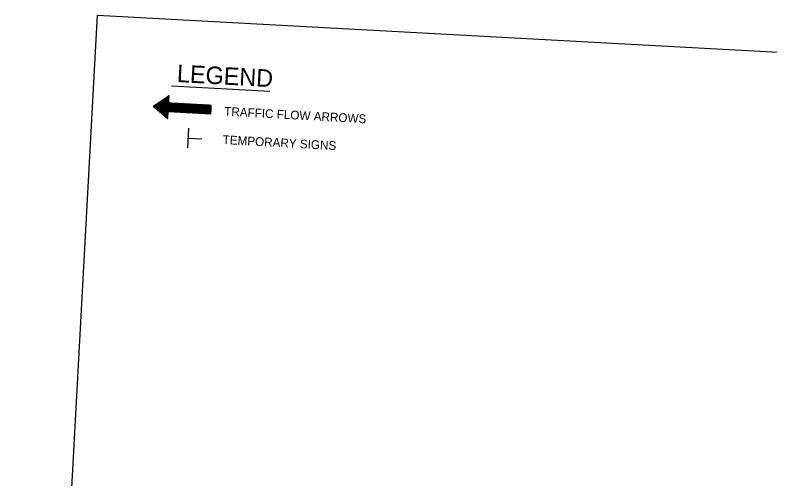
# Model space of a CAD drawing. Extents: x 879461 to 881100, y 1566470 to 1567598.
# Drawn here: x 879461 to 879979, y 1567279 to 1567598 of the extents above; entities that cross this region are included whole.
import ezdxf

# ---------------------------------------------------------------- set-up
doc = ezdxf.new("R2010")
doc.units = 0
for name, color, linetype in [('R_Annotation', 7, 'Continuous'), ('R_Draft', 7, 'Continuous'), ('R_Legend_MOT', 7, 'Continuous'), ('R_No Plot', 7, 'Continuous')]:
    doc.layers.add(name, color=color, linetype=linetype)

msp = doc.modelspace()

# ---------------------------------------------------------------- linework, layer by layer
at = {"layer": 'R_Annotation'}
for p, q in [((879560.83, 1567538.32), (879556.61, 1567534.53)), ((879561.47, 1567538.76), (879556.69, 1567534.47)), ((879562.11, 1567539.2), (879556.77, 1567534.4)), ((879562.75, 1567539.64), (879556.84, 1567534.34)), ((879563.4, 1567540.08), (879556.92, 1567534.27)), ((879564.04, 1567540.52), (879557, 1567534.21)), ((879564.68, 1567540.96), (879557.07, 1567534.14)), ((879565.32, 1567541.4), (879557.15, 1567534.07)), ((879565.96, 1567541.84), (879557.23, 1567534.01)), ((879566.6, 1567542.28), (879557.3, 1567533.94)), ((879566.81, 1567542.34), (879557.38, 1567533.88)), ((879566.8, 1567542.2), (879557.46, 1567533.81)), ((879566.8, 1567542.05), (879557.53, 1567533.74)), ((879566.79, 1567541.91), (879557.61, 1567533.68)), ((879566.78, 1567541.77), (879557.68, 1567533.61)), ((879566.77, 1567541.63), (879557.76, 1567533.55)), ((879566.77, 1567541.49), (879557.84, 1567533.48)), ((879566.76, 1567541.35), (879557.91, 1567533.42)), ((879566.75, 1567541.21), (879557.99, 1567533.35)), ((879566.74, 1567541.07), (879558.07, 1567533.28)), ((879566.74, 1567540.92), (879558.14, 1567533.22)), ((879566.73, 1567540.78), (879558.22, 1567533.15)), ((879566.72, 1567540.64), (879558.3, 1567533.09)), ((879566.71, 1567540.5), (879558.37, 1567533.02)), ((879566.71, 1567540.36), (879558.45, 1567532.96)), ((879566.7, 1567540.22), (879558.52, 1567532.89)), ((879566.69, 1567540.08), (879558.6, 1567532.82)), ((879566.68, 1567539.94), (879558.68, 1567532.76)), ((879566.67, 1567539.79), (879558.75, 1567532.69)), ((879566.67, 1567539.65), (879558.83, 1567532.63)), ((879566.66, 1567539.51), (879558.91, 1567532.56)), ((879566.65, 1567539.37), (879558.98, 1567532.49)), ((879566.64, 1567539.23), (879559.06, 1567532.43)), ((879566.64, 1567539.09), (879559.14, 1567532.36)), ((879566.63, 1567538.95), (879559.21, 1567532.3)), ((879566.62, 1567538.81), (879559.29, 1567532.23)), ((879566.61, 1567538.67), (879559.37, 1567532.17)), ((879566.61, 1567538.52), (879559.44, 1567532.1)), ((879566.6, 1567538.38), (879559.52, 1567532.03)), ((879566.59, 1567538.24), (879559.59, 1567531.97)), ((879556.34, 1567535.23), (879556.08, 1567534.99)), ((879556.98, 1567535.67), (879556.16, 1567534.93)), ((879557.62, 1567536.11), (879556.23, 1567534.86)), ((879558.27, 1567536.55), (879556.31, 1567534.8)), ((879558.91, 1567536.99), (879556.39, 1567534.73)), ((879559.55, 1567537.43), (879556.46, 1567534.67)), ((879560.19, 1567537.87), (879556.54, 1567534.6)), ((879566.58, 1567538.1), (879559.67, 1567531.9)), ((879566.57, 1567537.96), (879559.75, 1567531.84)), ((879566.57, 1567537.82), (879559.82, 1567531.77)), ((879566.56, 1567537.68), (879559.9, 1567531.7)), ((879566.55, 1567537.54), (879559.98, 1567531.64)), ((879566.6, 1567537.45), (879560.05, 1567531.57)), ((879566.74, 1567537.44), (879560.13, 1567531.51)), ((879566.89, 1567537.43), (879560.21, 1567531.44)), ((879567.03, 1567537.42), (879560.28, 1567531.38)), ((879567.17, 1567537.42), (879560.36, 1567531.31)), ((879567.31, 1567537.41), (879560.44, 1567531.24)), ((879567.45, 1567537.4), (879560.51, 1567531.18)), ((879567.59, 1567537.39), (879560.59, 1567531.11)), ((879567.73, 1567537.39), (879560.66, 1567531.05)), ((879567.87, 1567537.38), (879560.74, 1567530.98)), ((879568.02, 1567537.37), (879560.82, 1567530.92)), ((879568.16, 1567537.36), (879560.89, 1567530.85)), ((879568.3, 1567537.36), (879560.97, 1567530.78)), ((879568.44, 1567537.35), (879561.05, 1567530.72)), ((879568.58, 1567537.34), (879561.12, 1567530.65)), ((879568.72, 1567537.33), (879561.2, 1567530.59)), ((879568.86, 1567537.32), (879561.28, 1567530.52)), ((879569, 1567537.32), (879561.35, 1567530.45)), ((879569.15, 1567537.31), (879561.43, 1567530.39)), ((879569.29, 1567537.3), (879561.51, 1567530.32)), ((879569.43, 1567537.29), (879561.58, 1567530.26)), ((879569.57, 1567537.29), (879561.66, 1567530.19)), ((879569.71, 1567537.28), (879561.73, 1567530.13)), ((879569.85, 1567537.27), (879561.81, 1567530.06)), ((879569.99, 1567537.26), (879561.89, 1567529.99)), ((879570.13, 1567537.26), (879561.96, 1567529.93)), ((879570.27, 1567537.25), (879562.04, 1567529.86)), ((879570.42, 1567537.24), (879562.12, 1567529.8)), ((879570.56, 1567537.23), (879562.19, 1567529.73)), ((879570.7, 1567537.22), (879562.27, 1567529.67)), ((879570.84, 1567537.22), (879562.35, 1567529.6)), ((879570.98, 1567537.21), (879562.42, 1567529.53)), ((879571.12, 1567537.2), (879562.5, 1567529.47)), ((879571.26, 1567537.19), (879562.57, 1567529.4)), ((879571.4, 1567537.19), (879562.65, 1567529.34)), ((879571.55, 1567537.18), (879562.73, 1567529.27)), ((879571.69, 1567537.17), (879562.8, 1567529.2)), ((879571.83, 1567537.16), (879562.88, 1567529.14)), ((879571.97, 1567537.16), (879562.96, 1567529.07)), ((879572.11, 1567537.15), (879563.03, 1567529.01)), ((879572.25, 1567537.14), (879563.11, 1567528.94)), ((879572.39, 1567537.13), (879563.19, 1567528.88)), ((879572.53, 1567537.13), (879566.23, 1567531.47)), ((879572.68, 1567537.12), (879566.37, 1567531.47)), ((879572.82, 1567537.11), (879566.52, 1567531.46)), ((879572.96, 1567537.1), (879566.66, 1567531.45)), ((879573.1, 1567537.09), (879566.8, 1567531.44)), ((879573.24, 1567537.09), (879566.94, 1567531.44)), ((879573.38, 1567537.08), (879567.08, 1567531.43)), ((879573.52, 1567537.07), (879567.22, 1567531.42)), ((879573.66, 1567537.06), (879567.36, 1567531.41)), ((879573.81, 1567537.06), (879567.5, 1567531.41)), ((879573.95, 1567537.05), (879567.65, 1567531.4)), ((879574.09, 1567537.04), (879567.79, 1567531.39)), ((879574.23, 1567537.03), (879567.93, 1567531.38)), ((879574.37, 1567537.03), (879568.07, 1567531.37)), ((879574.51, 1567537.02), (879568.21, 1567531.37)), ((879574.65, 1567537.01), (879568.35, 1567531.36)), ((879574.79, 1567537), (879568.49, 1567531.35)), ((879574.93, 1567536.99), (879568.63, 1567531.34)), ((879575.08, 1567536.99), (879568.78, 1567531.34)), ((879575.22, 1567536.98), (879568.92, 1567531.33)), ((879575.36, 1567536.97), (879569.06, 1567531.32)), ((879575.5, 1567536.96), (879569.2, 1567531.31)), ((879575.64, 1567536.96), (879569.34, 1567531.31)), ((879575.78, 1567536.95), (879569.48, 1567531.3)), ((879575.92, 1567536.94), (879569.62, 1567531.29)), ((879576.06, 1567536.93), (879569.76, 1567531.28)), ((879576.21, 1567536.93), (879569.9, 1567531.27)), ((879576.35, 1567536.92), (879570.05, 1567531.27)), ((879576.49, 1567536.91), (879570.19, 1567531.26)), ((879576.63, 1567536.9), (879570.33, 1567531.25)), ((879576.77, 1567536.89), (879570.47, 1567531.24)), ((879576.91, 1567536.89), (879570.61, 1567531.24)), ((879577.05, 1567536.88), (879570.75, 1567531.23)), ((879577.19, 1567536.87), (879570.89, 1567531.22)), ((879577.34, 1567536.86), (879571.03, 1567531.21)), ((879577.48, 1567536.86), (879571.18, 1567531.21)), ((879577.62, 1567536.85), (879571.32, 1567531.2)), ((879577.76, 1567536.84), (879571.46, 1567531.19)), ((879577.9, 1567536.83), (879571.6, 1567531.18)), ((879578.04, 1567536.83), (879571.74, 1567531.17)), ((879578.18, 1567536.82), (879571.88, 1567531.17)), ((879578.32, 1567536.81), (879572.02, 1567531.16)), ((879578.47, 1567536.8), (879572.16, 1567531.15)), ((879578.61, 1567536.79), (879572.31, 1567531.14)), ((879578.75, 1567536.79), (879572.45, 1567531.14)), ((879578.89, 1567536.78), (879572.59, 1567531.13)), ((879579.03, 1567536.77), (879572.73, 1567531.12)), ((879579.17, 1567536.76), (879572.87, 1567531.11)), ((879579.31, 1567536.76), (879573.01, 1567531.11)), ((879579.45, 1567536.75), (879573.15, 1567531.1)), ((879579.59, 1567536.74), (879573.29, 1567531.09)), ((879579.74, 1567536.73), (879573.44, 1567531.08)), ((879579.88, 1567536.73), (879573.58, 1567531.07)), ((879580.02, 1567536.72), (879573.72, 1567531.07)), ((879580.16, 1567536.71), (879573.86, 1567531.06)), ((879580.3, 1567536.7), (879574, 1567531.05)), ((879580.44, 1567536.7), (879574.14, 1567531.04)), ((879580.58, 1567536.69), (879574.28, 1567531.04)), ((879580.72, 1567536.68), (879574.42, 1567531.03)), ((879580.87, 1567536.67), (879574.56, 1567531.02)), ((879581.01, 1567536.66), (879574.71, 1567531.01)), ((879581.15, 1567536.66), (879574.85, 1567531.01)), ((879581.29, 1567536.65), (879574.99, 1567531)), ((879581.43, 1567536.64), (879575.13, 1567530.99)), ((879581.57, 1567536.63), (879575.27, 1567530.98)), ((879581.71, 1567536.63), (879575.41, 1567530.98)), ((879581.85, 1567536.62), (879575.55, 1567530.97)), ((879582, 1567536.61), (879575.69, 1567530.96)), ((879582.14, 1567536.6), (879575.84, 1567530.95)), ((879582.28, 1567536.6), (879575.98, 1567530.94)), ((879582.42, 1567536.59), (879576.12, 1567530.94)), ((879582.56, 1567536.58), (879576.26, 1567530.93)), ((879582.7, 1567536.57), (879576.4, 1567530.92)), ((879582.84, 1567536.56), (879576.54, 1567530.91)), ((879582.98, 1567536.56), (879576.68, 1567530.91)), ((879583.13, 1567536.55), (879576.82, 1567530.9)), ((879583.27, 1567536.54), (879576.97, 1567530.89)), ((879583.41, 1567536.53), (879577.11, 1567530.88)), ((879583.55, 1567536.53), (879577.25, 1567530.88)), ((879583.69, 1567536.52), (879577.39, 1567530.87)), ((879583.83, 1567536.51), (879577.53, 1567530.86)), ((879583.97, 1567536.5), (879577.67, 1567530.85)), ((879584.11, 1567536.5), (879577.81, 1567530.84)), ((879584.25, 1567536.49), (879577.95, 1567530.84)), ((879584.4, 1567536.48), (879578.1, 1567530.83)), ((879584.54, 1567536.47), (879578.24, 1567530.82)), ((879584.68, 1567536.46), (879578.38, 1567530.81)), ((879584.82, 1567536.46), (879578.52, 1567530.81)), ((879584.96, 1567536.45), (879578.66, 1567530.8)), ((879585.1, 1567536.44), (879578.8, 1567530.79)), ((879585.24, 1567536.43), (879578.94, 1567530.78)), ((879585.38, 1567536.43), (879579.08, 1567530.78)), ((879585.53, 1567536.42), (879579.22, 1567530.77)), ((879585.67, 1567536.41), (879579.37, 1567530.76)), ((879585.81, 1567536.4), (879579.51, 1567530.75)), ((879585.95, 1567536.4), (879579.65, 1567530.74)), ((879586.09, 1567536.39), (879579.79, 1567530.74)), ((879586.23, 1567536.38), (879579.93, 1567530.73)), ((879586.37, 1567536.37), (879580.07, 1567530.72)), ((879586.51, 1567536.36), (879580.21, 1567530.71)), ((879586.66, 1567536.36), (879580.35, 1567530.71)), ((879586.8, 1567536.35), (879580.5, 1567530.7)), ((879586.94, 1567536.34), (879580.64, 1567530.69)), ((879587.08, 1567536.33), (879580.78, 1567530.68)), ((879587.22, 1567536.33), (879580.92, 1567530.68)), ((879587.36, 1567536.32), (879581.06, 1567530.67)), ((879587.5, 1567536.31), (879581.2, 1567530.66)), ((879587.64, 1567536.3), (879581.34, 1567530.65)), ((879587.79, 1567536.3), (879581.48, 1567530.64)), ((879587.93, 1567536.29), (879581.63, 1567530.64)), ((879588.07, 1567536.28), (879581.77, 1567530.63)), ((879588.21, 1567536.27), (879581.91, 1567530.62)), ((879588.35, 1567536.26), (879582.05, 1567530.61)), ((879588.49, 1567536.26), (879582.19, 1567530.61)), ((879588.63, 1567536.25), (879582.33, 1567530.6)), ((879588.77, 1567536.24), (879582.47, 1567530.59)), ((879588.91, 1567536.23), (879582.61, 1567530.58)), ((879589.06, 1567536.23), (879582.76, 1567530.58)), ((879589.2, 1567536.22), (879582.9, 1567530.57)), ((879589.34, 1567536.21), (879583.04, 1567530.56)), ((879589.48, 1567536.2), (879583.18, 1567530.55)), ((879589.62, 1567536.2), (879583.32, 1567530.55)), ((879589.76, 1567536.19), (879583.46, 1567530.54)), ((879589.9, 1567536.18), (879583.6, 1567530.53)), ((879590.04, 1567536.17), (879583.74, 1567530.52)), ((879590.19, 1567536.17), (879583.88, 1567530.51)), ((879590.33, 1567536.16), (879584.03, 1567530.51)), ((879590.47, 1567536.15), (879584.17, 1567530.5)), ((879590.61, 1567536.14), (879584.31, 1567530.49)), ((879590.75, 1567536.13), (879584.45, 1567530.48)), ((879590.89, 1567536.13), (879584.59, 1567530.48)), ((879591.03, 1567536.12), (879584.73, 1567530.47)), ((879591.17, 1567536.11), (879584.87, 1567530.46)), ((879591.32, 1567536.1), (879585.01, 1567530.45)), ((879591.46, 1567536.1), (879585.16, 1567530.45)), ((879591.6, 1567536.09), (879585.3, 1567530.44)), ((879591.74, 1567536.08), (879585.44, 1567530.43)), ((879591.88, 1567536.07), (879585.58, 1567530.42)), ((879592.02, 1567536.07), (879585.72, 1567530.41)), ((879592.16, 1567536.06), (879585.86, 1567530.41)), ((879592.3, 1567536.05), (879586, 1567530.4)), ((879592.45, 1567536.04), (879586.14, 1567530.39)), ((879592.59, 1567536.03), (879586.29, 1567530.38)), ((879592.73, 1567536.03), (879586.43, 1567530.38)), ((879592.87, 1567536.02), (879586.57, 1567530.37)), ((879593.01, 1567536.01), (879586.71, 1567530.36)), ((879593.15, 1567536), (879586.85, 1567530.35)), ((879593.29, 1567536), (879586.99, 1567530.35)), ((879593.43, 1567535.99), (879587.13, 1567530.34)), ((879593.57, 1567535.98), (879587.27, 1567530.33)), ((879593.72, 1567535.97), (879587.42, 1567530.32)), ((879593.86, 1567535.97), (879587.56, 1567530.31)), ((879594, 1567535.96), (879587.7, 1567530.31)), ((879594.14, 1567535.95), (879587.84, 1567530.3)), ((879594.28, 1567535.94), (879587.98, 1567530.29)), ((879594.42, 1567535.93), (879588.12, 1567530.28)), ((879594.56, 1567535.93), (879588.26, 1567530.28)), ((879594.7, 1567535.92), (879588.4, 1567530.27)), ((879594.85, 1567535.91), (879588.54, 1567530.26)), ((879594.99, 1567535.9), (879588.69, 1567530.25)), ((879595.13, 1567535.9), (879588.83, 1567530.25)), ((879595.27, 1567535.89), (879588.97, 1567530.24)), ((879595.41, 1567535.88), (879589.11, 1567530.23)), ((879595.55, 1567535.87), (879589.25, 1567530.22)), ((879595.69, 1567535.87), (879589.39, 1567530.21)), ((879595.83, 1567535.86), (879589.53, 1567530.21)), ((879595.84, 1567535.73), (879589.67, 1567530.2)), ((879595.84, 1567535.59), (879589.82, 1567530.19)), ((879595.83, 1567535.45), (879589.96, 1567530.18)), ((879595.82, 1567535.31), (879590.1, 1567530.18)), ((879595.81, 1567535.17), (879590.24, 1567530.17)), ((879595.81, 1567535.03), (879590.38, 1567530.16)), ((879595.8, 1567534.89), (879590.52, 1567530.15)), ((879595.79, 1567534.74), (879590.66, 1567530.15)), ((879595.78, 1567534.6), (879590.8, 1567530.14)), ((879595.77, 1567534.46), (879590.95, 1567530.13)), ((879595.77, 1567534.32), (879591.09, 1567530.12)), ((879595.76, 1567534.18), (879591.23, 1567530.12)), ((879595.75, 1567534.04), (879591.37, 1567530.11)), ((879595.74, 1567533.9), (879591.51, 1567530.1)), ((879595.74, 1567533.76), (879591.65, 1567530.09)), ((879595.73, 1567533.61), (879591.79, 1567530.08)), ((879595.72, 1567533.47), (879591.93, 1567530.08)), ((879595.71, 1567533.33), (879592.08, 1567530.07)), ((879595.71, 1567533.19), (879592.22, 1567530.06)), ((879595.7, 1567533.05), (879592.36, 1567530.05)), ((879566.22, 1567531.46), (879563.26, 1567528.81)), ((879566.21, 1567531.32), (879563.34, 1567528.74)), ((879566.21, 1567531.18), (879563.42, 1567528.68)), ((879566.2, 1567531.04), (879563.49, 1567528.61)), ((879566.19, 1567530.9), (879563.57, 1567528.55)), ((879566.18, 1567530.76), (879563.64, 1567528.48)), ((879566.18, 1567530.62), (879563.72, 1567528.42)), ((879566.17, 1567530.47), (879563.8, 1567528.35)), ((879566.16, 1567530.33), (879563.87, 1567528.28)), ((879566.15, 1567530.19), (879563.95, 1567528.22)), ((879566.14, 1567530.05), (879564.03, 1567528.15)), ((879566.14, 1567529.91), (879564.1, 1567528.09)), ((879566.13, 1567529.77), (879564.18, 1567528.02)), ((879566.12, 1567529.63), (879564.26, 1567527.95)), ((879566.11, 1567529.49), (879564.33, 1567527.89)), ((879566.11, 1567529.35), (879564.41, 1567527.82)), ((879566.1, 1567529.2), (879564.49, 1567527.76)), ((879566.09, 1567529.06), (879564.56, 1567527.69)), ((879566.08, 1567528.92), (879564.64, 1567527.63)), ((879566.08, 1567528.78), (879564.71, 1567527.56)), ((879566.07, 1567528.64), (879564.79, 1567527.49)), ((879566.06, 1567528.5), (879564.87, 1567527.43)), ((879566.05, 1567528.36), (879564.94, 1567527.36)), ((879566.04, 1567528.22), (879565.02, 1567527.3)), ((879566.04, 1567528.07), (879565.1, 1567527.23)), ((879566.03, 1567527.93), (879565.17, 1567527.17)), ((879566.02, 1567527.79), (879565.25, 1567527.1)), ((879595.69, 1567532.91), (879592.5, 1567530.05)), ((879595.68, 1567532.77), (879592.64, 1567530.04)), ((879595.68, 1567532.63), (879592.78, 1567530.03)), ((879595.67, 1567532.48), (879592.92, 1567530.02)), ((879595.66, 1567532.34), (879593.06, 1567530.02)), ((879595.65, 1567532.2), (879593.2, 1567530.01)), ((879595.64, 1567532.06), (879593.35, 1567530)), ((879595.64, 1567531.92), (879593.49, 1567529.99)), ((879595.63, 1567531.78), (879593.63, 1567529.98)), ((879595.62, 1567531.64), (879593.77, 1567529.98)), ((879595.61, 1567531.5), (879593.91, 1567529.97)), ((879595.61, 1567531.35), (879594.05, 1567529.96)), ((879595.6, 1567531.21), (879594.19, 1567529.95)), ((879595.59, 1567531.07), (879594.33, 1567529.95)), ((879595.58, 1567530.93), (879594.48, 1567529.94)), ((879595.58, 1567530.79), (879594.62, 1567529.93)), ((879595.57, 1567530.65), (879594.76, 1567529.92)), ((879595.56, 1567530.51), (879594.9, 1567529.92)), ((879595.55, 1567530.37), (879595.04, 1567529.91)), ((879595.54, 1567530.23), (879595.18, 1567529.9)), ((879595.54, 1567530.08), (879595.32, 1567529.89)), ((879595.53, 1567529.94), (879595.46, 1567529.88)), ((879566.01, 1567527.65), (879565.33, 1567527.03)), ((879566.01, 1567527.51), (879565.4, 1567526.97)), ((879566, 1567527.37), (879565.48, 1567526.9)), ((879565.99, 1567527.23), (879565.55, 1567526.84)), ((879565.98, 1567527.09), (879565.63, 1567526.77)), ((879565.98, 1567526.94), (879565.71, 1567526.7)), ((879565.97, 1567526.8), (879565.78, 1567526.64)), ((879565.96, 1567526.66), (879565.86, 1567526.57)), ((879565.95, 1567526.52), (879565.94, 1567526.51))]:
    msp.add_line(p, q, dxfattribs=at)
at = {"layer": 'R_Draft'}
for p, q in [((879556.04, 1567535.03), (879566.82, 1567542.43)), ((879566.55, 1567537.45), (879566.82, 1567542.43)), ((879565.95, 1567526.5), (879556.04, 1567535.03)), ((879566.55, 1567537.45), (879595.85, 1567535.86)), ((879595.53, 1567529.88), (879595.85, 1567535.86)), ((879565.95, 1567526.5), (879566.22, 1567531.47)), ((879566.22, 1567531.47), (879595.53, 1567529.88)), ((879579.62, 1567506.54), (879580.35, 1567519.98)), ((879580.18, 1567513.22), (879589.35, 1567512.72))]:
    msp.add_line(p, q, dxfattribs=at)
at = {"layer": 'R_Legend_MOT'}
msp.add_line((879568.52, 1567549.16), (879635.93, 1567545.49), dxfattribs=at)
at = {"layer": 'R_No Plot'}
msp.add_lwpolyline([(881099.91, 1567310.44), (881054.22, 1566470.26), (879461.22, 1566556.89), (879517.82, 1567597.67), (880700.13, 1567533.37), (880697.45, 1567484.05), (880874.78, 1567474.4), (880873.82, 1567456.58), (880891.99, 1567455.59), (880892.17, 1567458.84), (880969.72, 1567454.62)], dxfattribs=at)

# ---------------------------------------------------------------- texts
at = {"layer": 'R_Legend_MOT'}
for s, height, p in [('LEGEND', 12, (879572.02, 1567551.77)), ('TRAFFIC FLOW ARROWS', 6, (879604.54, 1567528.73)), ('TEMPORARY SIGNS', 6, (879603.48, 1567509.26))]:
    msp.add_text(s, height=height, rotation=356.8871, dxfattribs=at).set_placement(p)

doc.saveas('drawing.dxf')
